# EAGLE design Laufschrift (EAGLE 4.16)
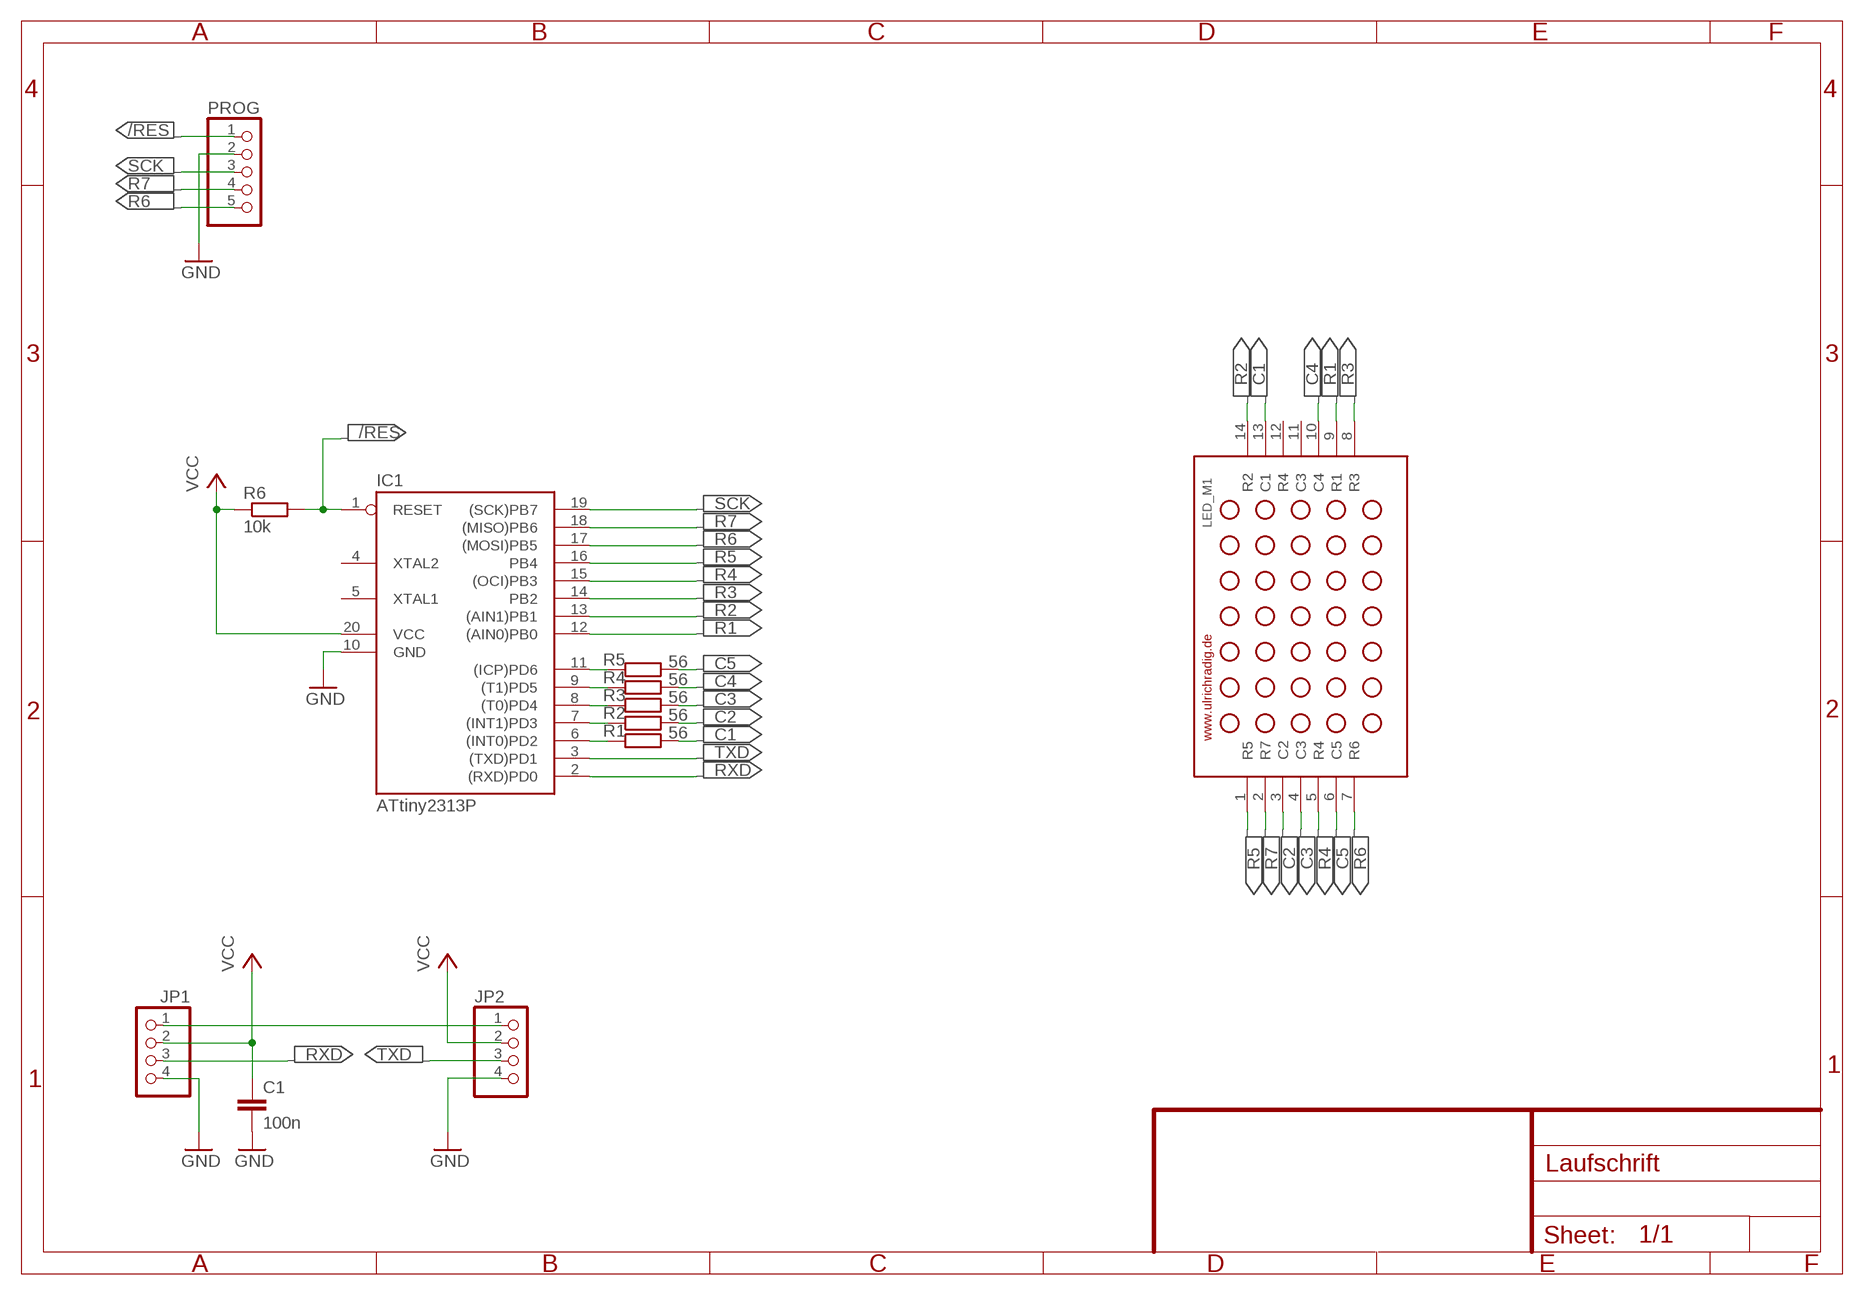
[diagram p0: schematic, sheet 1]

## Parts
C1  100n  C-EU025-025X050  [C025-025X050]
IC1  ATtiny2313P  AT90S2313P  [DIL20]
JP1  PINHD-1X4  [1X04]
JP2  PINHD-1X4  [1X04]
LED_M1  TC20-11  [LED_M]
PROG  PINHD-1X5  [1X05]
R1  56  R-EU_0207/10  [0207/10]
R2  56  R-EU_0207/10  [0207/10]
R3  56  R-EU_0207/10  [0207/10]
R4  56  R-EU_0207/10  [0207/10]
R5  56  R-EU_0207/10  [0207/10]
R6  10k  R-EU_0207/10  [0207/10]

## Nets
/RES: IC1.1(RESET) PROG.1 R6.2
C1: LED_M1.13(C1) R1.2
C2: LED_M1.3(C2) R2.2
C3: LED_M1.4(C3) R3.2
C4: LED_M1.10(C4) R4.2
C5: LED_M1.6(C5) R5.2
GND: C1.2 IC1.10(GND) JP1.4 JP2.4 PROG.2
N$5: JP1.1 JP2.1
N$8: IC1.11((ICP)PD6) R5.1
N$9: IC1.9((T1)PD5) R4.1
N$10: IC1.8((T0)PD4) R3.1
N$11: IC1.7((INT1)PD3) R2.1
N$12: IC1.6((INT0)PD2) R1.1
R1: IC1.12((AIN0)PB0) LED_M1.9(R1)
R2: IC1.13((AIN1)PB1) LED_M1.14(R2)
R3: IC1.14(PB2) LED_M1.8(R3)
R4: IC1.15((OCI)PB3) LED_M1.5(R4)
R5: IC1.16(PB4) LED_M1.1(R5)
R6: IC1.17((MOSI)PB5) LED_M1.7(R6) PROG.5
R7: IC1.18((MISO)PB6) LED_M1.2(R7) PROG.4
RXD: IC1.2((RXD)PD0) JP1.3
SCK: IC1.19((SCK)PB7) PROG.3
TXD: IC1.3((TXD)PD1) JP2.3
VCC: C1.1 IC1.20(VCC) JP1.2 JP2.2 R6.1
Unconnected: IC1.4(XTAL2) IC1.5(XTAL1) LED_M1.11(C3) LED_M1.12(R4)

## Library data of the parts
C1 = rcl:C-EU: CAPACITOR, European symbol
IC1 = atmel:AT90S2313: MICROCONTROLLER 2 Kbytes FLASH 128 bytes SRAM 128 bytes EEPROM UART
JP1 JP2 = pinhead:PINHD-1X4: PIN HEADER
LED_M1 = led_matrix:TC20-11
PROG = pinhead:PINHD-1X5: PIN HEADER
R1-R6 = rcl:R-EU_: RESISTOR, European symbol

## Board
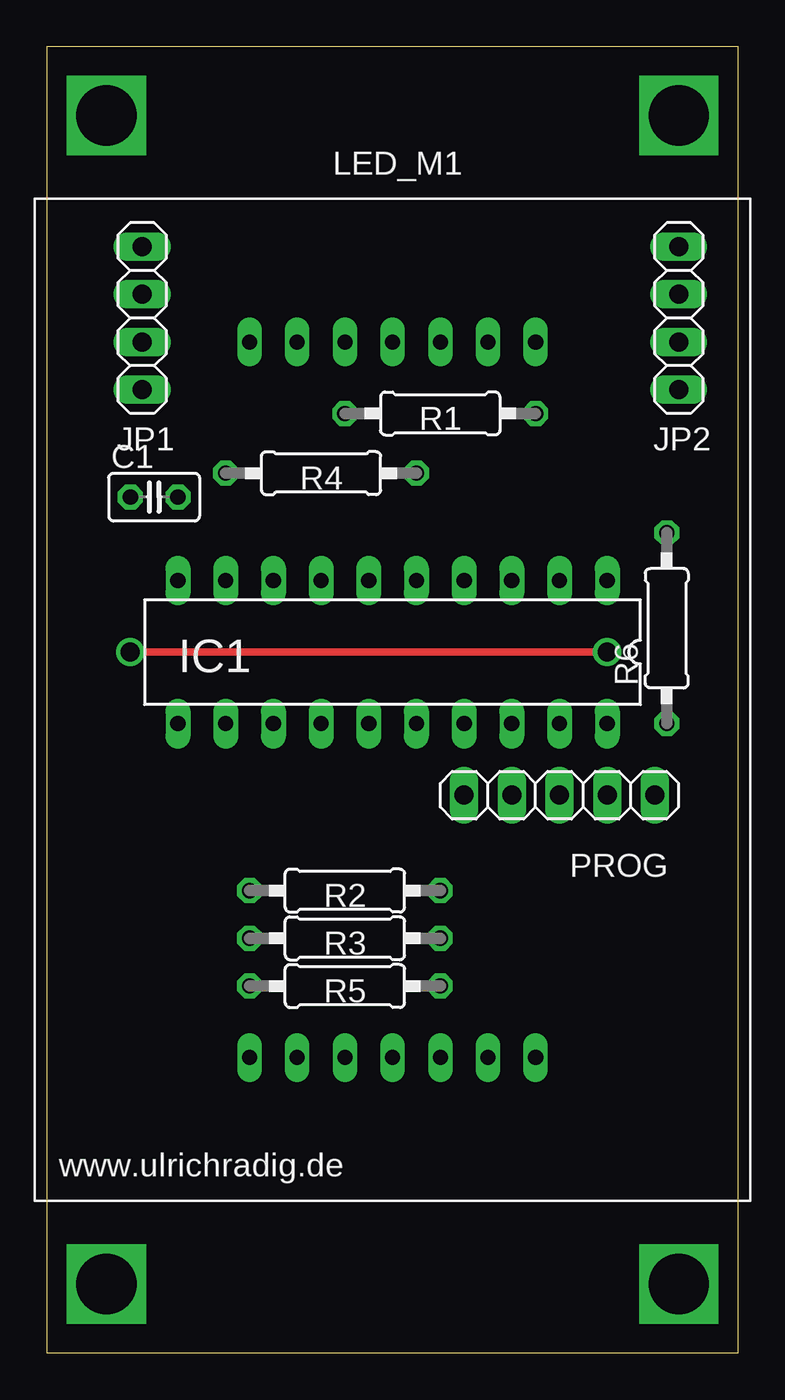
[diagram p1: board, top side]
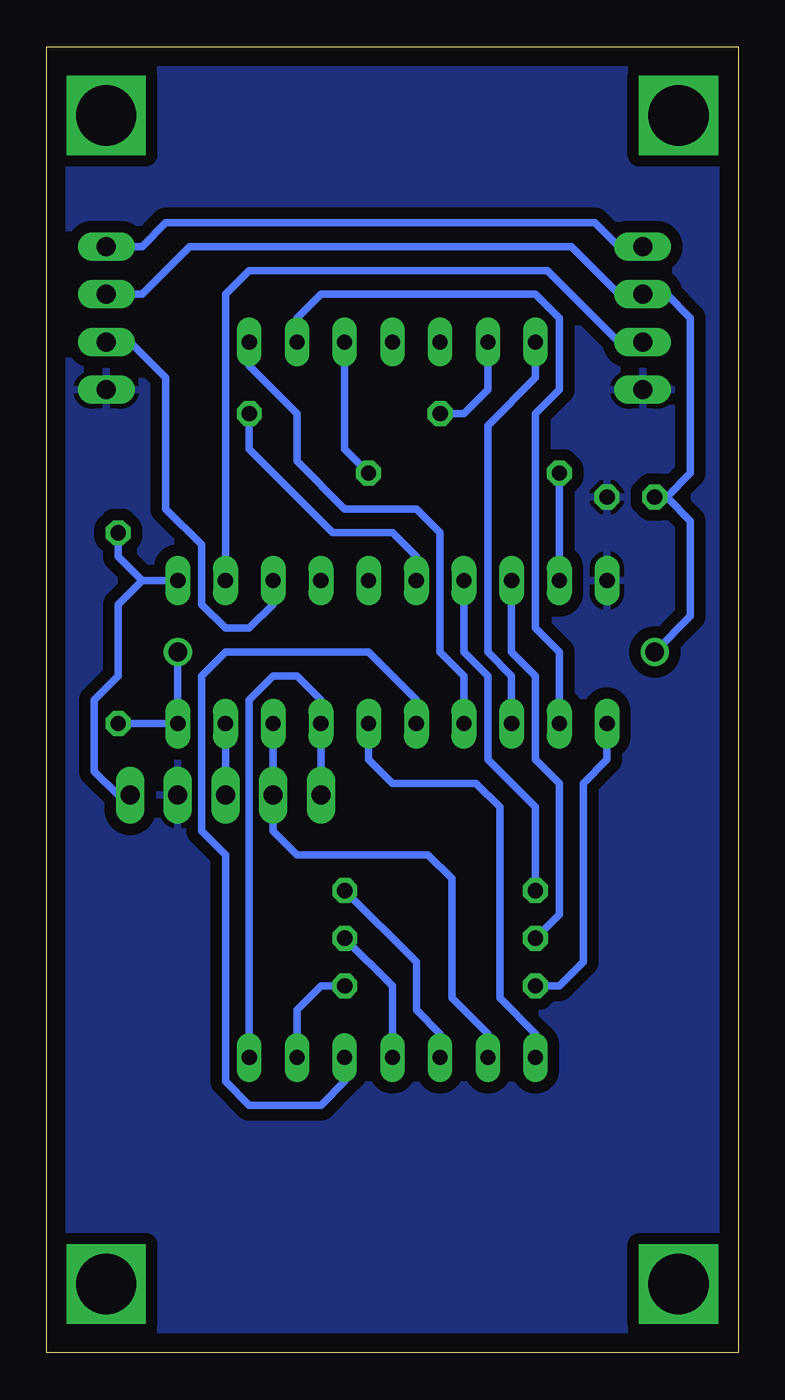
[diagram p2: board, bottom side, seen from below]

Size 36.81 x 69.52 mm. Coordinates in mm from the lower left corner, seen from the top.
Outline: 0,0 36.81,0 36.81,69.52 0,69.52 0,0
Copper layers (1*16): Top 0.035mm / dielectric 1.5mm / Bottom 0.035mm
Design rules "default": minimum track width 10mil, minimum drill 24mil, track to track 8mil, track to pad 8mil, pad to pad 8mil, via to via 8mil, smd to smd 8mil, copper to edge 40mil, drill to drill 8mil, minimum pad ring 10mil, minimum via ring 8mil, stop-mask expansion 4mil, vias tented up to drill 0mil, thermal gap 10mil

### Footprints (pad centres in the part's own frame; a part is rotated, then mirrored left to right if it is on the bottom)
C025-025X050 = drill 0.813 octagon: 1 -1.27,0; 2 1.27,0
DIL20 = drill 0.813 long: 1 -11.43,-3.81; 2 -8.89,-3.81; 3 -6.35,-3.81; 4 -3.81,-3.81; 5 -1.27,-3.81; 6 1.27,-3.81; 7 3.81,-3.81; 8 6.35,-3.81; 9 8.89,-3.81; 10 11.43,-3.81; 11 11.43,3.81; 12 8.89,3.81; 13 6.35,3.81; 14 3.81,3.81; 15 1.27,3.81; 16 -1.27,3.81; 17 -3.81,3.81; 18 -6.35,3.81; 19 -8.89,3.81; 20 -11.43,3.81
1X04 = drill 1.016 long: 1 -3.81,0; 2 -1.27,0; 3 1.27,0; 4 3.81,0
LED_M = drill 0.8 long: 1 11.43,7.62; 2 13.97,7.62; 3 16.51,7.62; 4 19.05,7.62; 5 21.59,7.62; 6 24.13,7.62; 7 26.67,7.62; 8 26.67,45.72; 9 24.13,45.72; 10 21.59,45.72; 11 19.05,45.72; 12 16.51,45.72; 13 13.97,45.72; 14 11.43,45.72
1X05 = drill 1.016 long: 1 -5.08,0; 2 -2.54,0; 3 0,0; 4 2.54,0; 5 5.08,0
0207/10 = drill 0.813 octagon: 1 -5.08,0; 2 5.08,0

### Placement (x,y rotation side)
C1  5.71,45.56 0 top
IC1  18.41,37.3 180 top
JP1  5.08,55.08 270 top
JP2  33.65,55.08 270 top
LED_M1  -0.64,8.09 0 top
PROG  27.3,29.68 180 top
R1  20.95,50 180 top
R2  15.87,24.6 0 top
R3  15.87,22.06 0 top
R4  14.6,46.83 0 top
R5  15.87,19.52 0 top
R6  33.02,38.57 90 top

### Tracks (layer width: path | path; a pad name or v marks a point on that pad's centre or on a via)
/RES
  Bottom 0.406: PROG.1 33.02,29.68 34.28,30.95 34.28,34.76 33.02,36.03 33.02,39.84 31.74,41.11 | 31.74,41.11 IC1.1 | R6.2 33.02,42.38 31.74,41.11
C1
  Bottom 0.406: R1.2 14.6,50 13.33,51.27 LED_M1.13
C2
  Bottom 0.406: LED_M1.3 15.87,16.98 17.14,18.25 17.14,20.79 R2.2
C3
  Bottom 0.406: LED_M1.4 18.41,19.52 R3.2
C4
  Bottom 0.406: R4.2 20.95,48.09 LED_M1.10
C5
  Bottom 0.406: R5.2 22.22,19.52 23.49,18.25 LED_M1.6
GND
  pour Bottom (isolate 0.61): -0.01,69.05 36.83,69.05 36.83,1.11 -0.01,1.11
N$1  (via drill 3.2)
  other vias: 3.17,65.88
N$2  (via drill 3.2)
  other vias: 33.65,65.88
N$3  (via drill 3.2)
  other vias: 3.17,3.64
N$4  (via drill 3.2)
  other vias: 33.65,3.64
N$5
  Bottom 0.406: JP1.1 6.35,58.89 7.62,60.16 30.47,60.16 31.74,58.89 JP2.1
N$8
  Bottom 0.406: R5.1 9.52,19.52 8.25,20.79 8.25,30.32 6.98,31.58 IC1.11
N$9
  Bottom 0.406: IC1.9 R4.1
N$10
  Bottom 0.406: R3.1 9.52,23.33 9.52,30.32 10.79,31.58 10.79,36.03 12.06,37.3 IC1.8
N$11
  Bottom 0.406: R2.1 10.79,29.04 13.33,31.58 13.33,36.03 14.6,37.3 IC1.7
N$12
  Bottom 0.406: IC1.6 17.14,42.38 18.41,43.65 21.59,43.65 26.03,48.09 R1.1
R1
  Bottom 0.406: IC1.12 9.52,37.3 10.79,38.57 10.79,50 9.52,51.27 9.52,55.08 10.79,56.35 22.22,56.35 23.49,55.08 LED_M1.9
R2
  Bottom 0.406: IC1.13 12.06,36.03 13.33,37.3 13.33,49.37 10.79,51.91 LED_M1.14
R3
  Bottom 0.406: IC1.14 14.6,36.03 15.87,37.3 15.87,43.65 17.14,44.92 20.95,44.92 23.49,47.46 23.49,50 26.03,52.54 LED_M1.8
R4
  Bottom 0.406: IC1.15 17.14,34.76 19.68,37.3 27.3,37.3 28.57,36.03 28.57,27.78 27.3,26.5 27.3,14.44 26.03,13.17 22.22,13.17 20.95,14.44 LED_M1.5
R5
  Bottom 0.406: LED_M1.1 10.79,16.98 12.7,18.89 12.7,29.04 13.96,30.32 18.41,30.32 19.68,31.58 IC1.16
R6
  Bottom 0.406: LED_M1.7 26.03,34.76 24.76,36.03 23.49,36.03 22.22,34.76 IC1.17 PROG.5
R7
  Bottom 0.406: IC1.18 PROG.4 24.76,27.78 23.49,26.5 16.5,26.5 15.23,25.24 15.23,18.89 13.33,16.98 LED_M1.2
RXD
  Bottom 0.406: JP1.3 6.35,53.81 10.15,57.62 26.03,57.62 27.3,56.35 IC1.2
SCK
  Bottom 0.406: PROG.3 IC1.19
TXD
  Bottom 0.406: IC1.3 24.76,39.84 26.03,38.57 27.3,38.57 28.57,39.84 28.57,43.02 30.47,44.92 30.47,51.91 32.38,53.81 JP2.3
VCC  (via drill 1)
  Top 0.406: v4.44,37.3 v29.84,37.3 v4.44,37.3
  Bottom 0.406: 31.74,56.35 29.2,58.89 8.88,58.89 6.35,56.35 JP1.2 3.81,56.35 2.53,55.08 2.53,46.83 3.81,45.56 | 31.74,56.35 JP2.2 | 31.74,56.35 34.92,56.35 | v29.84,37.3 IC1.20 R6.1 | v4.44,37.3 2.53,39.2 2.53,44.28 3.81,45.56 | 3.81,45.56 C1.1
